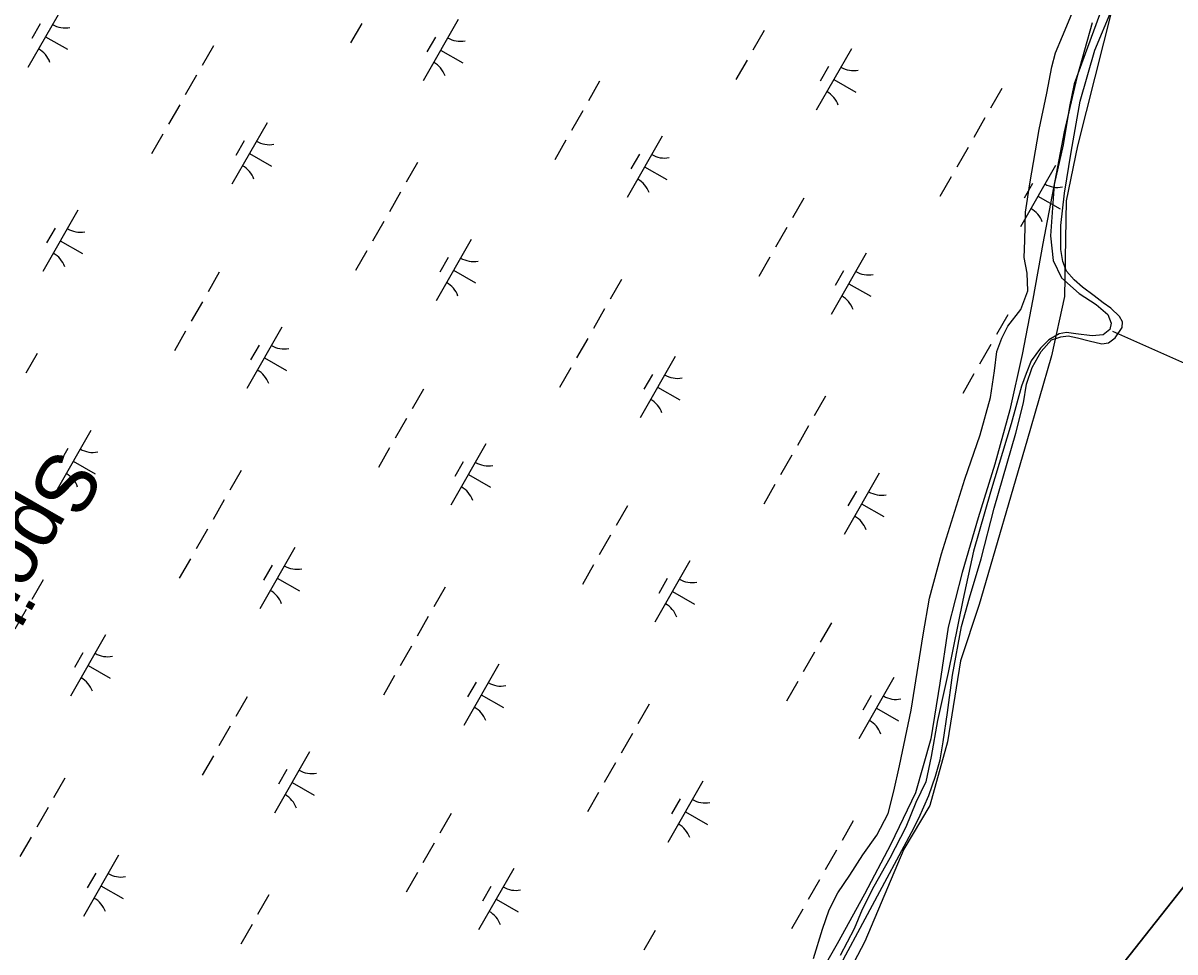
# Model space of a CAD drawing. Extents: x 3930721 to 3950824, y 220441 to 242861.
# Drawn here: x 3938674 to 3939489, y 229321 to 229978 of the extents above; entities that cross this region are included whole.
import ezdxf

# ---------------------------------------------------------------- set-up
doc = ezdxf.new("R2010")
doc.units = 0
for name, color, linetype in [('V-CHAN-SPOL', 7, 'Continuous'), ('V-LEVE-TOET', 7, 'Continuous'), ('V-RIVR-EDGE', 7, 'Continuous'), ('V-RIVR-JETY', 7, 'Continuous'), ('V-RRAP-FSHR', 7, 'Continuous'), ('V-TOPO-DPTH', 7, 'Continuous'), ('V-TOPO-MINR', 7, 'Continuous'), ('V-WETL-SWMP', 7, 'Continuous')]:
    doc.layers.add(name, color=color, linetype=linetype)

msp = doc.modelspace()

# ---------------------------------------------------------------- linework, layer by layer
at = {"layer": 'V-LEVE-TOET'}
msp.add_lwpolyline([(3939445.14, 229760.37), (3939506.58, 229733.14), (3939560.07, 229712.49), (3939562.56, 229705.25), (3939824.79, 229580.15)], dxfattribs=at)
at = {"layer": 'V-RIVR-EDGE'}
msp.add_lwpolyline([(3939444.95, 229988.74), (3939420.38, 229891.49), (3939412.2, 229852.59), (3939411.17, 229785.02), (3939401.96, 229743.05), (3939384.56, 229682.65), (3939350.77, 229566.97), (3939337.46, 229527.05), (3939328.25, 229469.72), (3939315.97, 229424.68), (3939297.54, 229393.97), (3939269.9, 229328.45), (3939213.6, 229220.96)], dxfattribs=at)
at = {"layer": 'V-RIVR-JETY'}
for points in [[(3939311.08, 229545.58), (3939315.67, 229571.36), (3939324.13, 229602.94), (3939340.55, 229655.78), (3939351.43, 229687.07), (3939358.73, 229713.48), (3939361.57, 229732.28), (3939363.25, 229745.93), (3939366.79, 229755.35), (3939370.94, 229763.86), (3939380.2, 229775.76), (3939385.21, 229788.83), (3939384.79, 229801.54), (3939382.55, 229812.42), (3939383.04, 229824.54), (3939383.44, 229844.52), (3939386.57, 229864.54), (3939393.14, 229903.05), (3939398.63, 229928.84), (3939402.08, 229947.34), (3939404.7, 229957.36), (3939409.73, 229969.22), (3939418.6, 229990.5)], [(3939435.92, 229984.32), (3939427.37, 229961.22)], [(3939427.37, 229961.22), (3939417.94, 229935.39), (3939414.77, 229919.32), (3939410.2, 229892.32), (3939403.83, 229864.11), (3939401.17, 229827.75), (3939403.16, 229810.51), (3939409.04, 229798.16), (3939421.56, 229787.08), (3939433.45, 229779.33), (3939441.69, 229772.15), (3939444.18, 229766.12), (3939443.31, 229761.57), (3939438.51, 229757.89), (3939430.64, 229757.2), (3939419.12, 229758.6), (3939412.46, 229759.44), (3939407.32, 229758.48), (3939400.1, 229754.17), (3939394.1, 229748.36), (3939387.53, 229739.51), (3939383.99, 229730.39), (3939380.75, 229721.58), (3939373.45, 229694.86), (3939358.8, 229646.58), (3939346.81, 229604.68), (3939339.29, 229570.09), (3939328.91, 229518.82), (3939321.39, 229484.84), (3939316.8, 229459.36), (3939313.04, 229441.46), (3939305.93, 229426.86), (3939298.84, 229409.53), (3939287.55, 229387.61), (3939276.25, 229367.52), (3939267.94, 229351.09), (3939262.33, 229337.41), (3939252.53, 229318.54)], [(3939233.48, 229316.53), (3939239.93, 229337.18), (3939244.63, 229350.85), (3939250.87, 229363.02), (3939259.22, 229375.52), (3939268.46, 229389.84), (3939278.31, 229403.87), (3939286.33, 229419.09), (3939290.41, 229434.87), (3939294.46, 229452.78), (3939302.54, 229492.21), (3939311.08, 229545.58)]]:
    msp.add_lwpolyline(points, dxfattribs=at)
at = {"layer": 'V-RRAP-FSHR'}
msp.add_lwpolyline([(3939430.76, 229978.49), (3939419.93, 229940), (3939410.89, 229901.37), (3939403.33, 229861.82), (3939395.88, 229822.46), (3939388.63, 229783.13), (3939381.24, 229743.82), (3939372.45, 229704.81), (3939361.79, 229666.27), (3939350.14, 229628.4), (3939338.64, 229589.69), (3939328.76, 229550.95), (3939323, 229511.38), (3939316.65, 229471.92), (3939305.64, 229433.66), (3939288.17, 229397.51), (3939269.61, 229362.1), (3939250.3, 229326.97), (3939230.51, 229292.21)], dxfattribs=at)
at = {"layer": 'V-TOPO-DPTH'}
msp.add_lwpolyline([(3939138.35, 228899.83), (3939165.62, 228949.61), (3939838.21, 229801.24), (3940275.57, 230709.64), (3940672.35, 231617.74), (3940572.03, 231858.55), (3940567.32, 231867.07), (3940561.52, 231871.8), (3940554.1, 231870.85), (3940545.59, 231866.11), (3940533.62, 231848.45), (3940521.9, 231830.62), (3940510.57, 231812.55), (3940499.49, 231794.3), (3940485.98, 231771.51), (3940470.36, 231745.8), (3940454.38, 231720.33), (3940437.86, 231695.21), (3940420.97, 231670.32), (3940394.26, 231631.89), (3940546.87, 231888.16), (3940838.91, 231677.12)], dxfattribs=at)
at = {"layer": 'V-TOPO-MINR'}
msp.add_lwpolyline([(3940394.26, 231631.89), (3940420.97, 231670.32), (3940437.86, 231695.21), (3940454.38, 231720.33), (3940470.36, 231745.8), (3940485.98, 231771.51), (3940499.49, 231794.3), (3940510.57, 231812.55), (3940521.9, 231830.62), (3940533.62, 231848.45), (3940545.59, 231866.11), (3940554.1, 231870.85), (3940561.52, 231871.8), (3940567.32, 231867.07), (3940572.03, 231858.55), (3940672.35, 231617.74), (3940275.57, 230709.64), (3939838.21, 229801.24), (3939165.62, 228949.61), (3939138.35, 228899.83)], dxfattribs=at)
at = {"layer": 'V-WETL-SWMP'}
for p, q in [((3938702.67, 229990.48), (3938677.82, 229947.09)), ((3938982.2, 229981.03), (3938957.35, 229937.64)), ((3939432.52, 229959.27), (3939444.71, 229987.99)), ((3938686.53, 229977.83), (3938680.56, 229967.42)), ((3938914.08, 229978.21), (3938906.13, 229964.33)), ((3939198.58, 229973.1), (3939190.63, 229959.22)), ((3938690.24, 229968.79), (3938705.86, 229959.84)), ((3938966.06, 229968.37), (3938960.1, 229957.96)), ((3938809.04, 229962.32), (3938801.08, 229948.43)), ((3938969.78, 229959.33), (3938985.4, 229950.39)), ((3939260.41, 229960.25), (3939235.56, 229916.86)), ((3939422.23, 229923.04), (3939432.52, 229959.27)), ((3939186.65, 229952.27), (3939178.7, 229938.39)), ((3938797.11, 229941.49), (3938789.16, 229927.61)), ((3939244.27, 229947.6), (3939238.31, 229937.19)), ((3939082.27, 229937.2), (3939074.32, 229923.32)), ((3939247.98, 229938.56), (3939263.6, 229929.61)), ((3939366.78, 229932.09), (3939358.83, 229918.2)), ((3938785.18, 229920.66), (3938777.23, 229906.78)), ((3939070.35, 229916.37), (3939062.4, 229902.49)), ((3939415.84, 229887.1), (3939422.23, 229923.04)), ((3938847.01, 229907.82), (3938822.16, 229864.43)), ((3939354.85, 229911.26), (3939346.9, 229897.38)), ((3938773.25, 229899.84), (3938765.3, 229885.95)), ((3938830.87, 229895.16), (3938824.91, 229884.75)), ((3939058.42, 229895.55), (3939050.47, 229881.66)), ((3939126.54, 229898.36), (3939101.69, 229854.97)), ((3938834.58, 229886.12), (3938850.2, 229877.18)), ((3939110.4, 229885.71), (3939104.44, 229875.29)), ((3939342.92, 229890.43), (3939334.97, 229876.55)), ((3939411.21, 229857.99), (3939415.84, 229887.1)), ((3938953.38, 229879.65), (3938945.43, 229865.77)), ((3939114.12, 229876.67), (3939129.74, 229867.72)), ((3939404.75, 229877.59), (3939379.9, 229834.2)), ((3939331, 229869.61), (3939323.04, 229855.72)), ((3938941.45, 229858.82), (3938933.5, 229844.94)), ((3939388.61, 229864.93), (3939382.65, 229854.52)), ((3939226.62, 229854.53), (3939218.66, 229840.65)), ((3939392.33, 229855.89), (3939407.95, 229846.95)), ((3939408.59, 229835.08), (3939411.21, 229857.99)), ((3938713.14, 229845.92), (3938688.29, 229802.54)), ((3938929.52, 229838), (3938921.57, 229824.11)), ((3939214.69, 229833.71), (3939206.74, 229819.82)), ((3939408.5, 229818.18), (3939408.59, 229835.08)), ((3938697, 229833.27), (3938691.04, 229822.86)), ((3938700.72, 229824.23), (3938716.34, 229815.29)), ((3938991.35, 229825.15), (3938966.5, 229781.76)), ((3939409.88, 229809.62), (3939408.5, 229818.18)), ((3938917.59, 229817.17), (3938909.64, 229803.29)), ((3938975.21, 229812.5), (3938969.25, 229802.08)), ((3939202.76, 229812.88), (3939194.81, 229799)), ((3939270.88, 229815.69), (3939246.03, 229772.31)), ((3939412.55, 229802.89), (3939409.88, 229809.62)), ((3938813.21, 229802.1), (3938805.26, 229788.21)), ((3938978.92, 229803.46), (3938994.54, 229794.51)), ((3939254.75, 229803.04), (3939248.78, 229792.63)), ((3939418.07, 229796.7), (3939412.55, 229802.89)), ((3939097.72, 229796.98), (3939089.77, 229783.1)), ((3939258.46, 229794), (3939274.08, 229785.06)), ((3939423.85, 229791.56), (3939418.07, 229796.7)), ((3939432.23, 229785.41), (3939423.85, 229791.56)), ((3939438.51, 229780.53), (3939432.23, 229785.41)), ((3938801.29, 229781.27), (3938793.33, 229767.39)), ((3939444.01, 229776.69), (3939438.51, 229780.53)), ((3939450.05, 229770.77), (3939444.01, 229776.69)), ((3939085.79, 229776.16), (3939077.84, 229762.27)), ((3939370.96, 229771.87), (3939363.01, 229757.98)), ((3939452.17, 229766.89), (3939450.05, 229770.77)), ((3938789.36, 229760.45), (3938781.41, 229746.56)), ((3938857.48, 229763.26), (3938832.63, 229719.87)), ((3939447.08, 229755.67), (3939451.95, 229762.99)), ((3939451.95, 229762.99), (3939452.17, 229766.89)), ((3939073.86, 229755.33), (3939065.91, 229741.45)), ((3939394.67, 229746.04), (3939401.87, 229754.17)), ((3939401.87, 229754.17), (3939408.6, 229756.32)), ((3939408.6, 229756.32), (3939413.79, 229757.15)), ((3939413.79, 229757.15), (3939420.31, 229755.65)), ((3939420.31, 229755.65), (3939428.65, 229753.66)), ((3939428.65, 229753.66), (3939437.51, 229751.41)), ((3939437.51, 229751.41), (3939442.18, 229752.24)), ((3939442.18, 229752.24), (3939447.08, 229755.67)), ((3938684.32, 229744.55), (3938676.37, 229730.66)), ((3938841.34, 229750.61), (3938835.38, 229740.19)), ((3939359.03, 229751.04), (3939351.08, 229737.16)), ((3939388.29, 229734.79), (3939394.67, 229746.04)), ((3938845.06, 229741.56), (3938860.68, 229732.62)), ((3939135.69, 229742.48), (3939110.84, 229699.1)), ((3939061.94, 229734.5), (3939053.98, 229720.62)), ((3939119.55, 229729.83), (3939113.59, 229719.42)), ((3939347.1, 229730.22), (3939339.15, 229716.33)), ((3939384.25, 229722.79), (3939388.29, 229734.79)), ((3939123.27, 229720.79), (3939138.89, 229711.84)), ((3939382.04, 229709.77), (3939384.25, 229722.79)), ((3938957.56, 229719.43), (3938949.6, 229705.55)), ((3939242.06, 229714.32), (3939234.11, 229700.43)), ((3939376.8, 229688.14), (3939382.04, 229709.77)), ((3938945.63, 229698.61), (3938937.68, 229684.72)), ((3938722.29, 229690.05), (3938697.44, 229646.66)), ((3939230.13, 229693.49), (3939222.18, 229679.61)), ((3939361.48, 229635.22), (3939376.8, 229688.14)), ((3939001.82, 229680.59), (3938976.97, 229637.2)), ((3938706.15, 229677.39), (3938700.19, 229666.98)), ((3938933.7, 229677.78), (3938925.75, 229663.9)), ((3939218.21, 229672.66), (3939210.25, 229658.78)), ((3938709.86, 229668.35), (3938725.48, 229659.41)), ((3938985.68, 229667.94), (3938979.72, 229657.53)), ((3938828.66, 229661.88), (3938820.71, 229648)), ((3938989.4, 229658.9), (3939005.02, 229649.95)), ((3939280.03, 229659.82), (3939255.18, 229616.43)), ((3939206.28, 229651.84), (3939198.33, 229637.95)), ((3939263.89, 229647.16), (3939257.93, 229636.75)), ((3938816.73, 229641.05), (3938808.78, 229627.17)), ((3939267.61, 229638.12), (3939283.23, 229629.18)), ((3939101.9, 229636.77), (3939093.95, 229622.88)), ((3939352.22, 229599.25), (3939361.48, 229635.22)), ((3938804.8, 229620.23), (3938796.85, 229606.34)), ((3939089.97, 229615.94), (3939082.02, 229602.06)), ((3938866.63, 229607.38), (3938841.78, 229563.99)), ((3938792.88, 229599.4), (3938784.92, 229585.52)), ((3939146.16, 229597.93), (3939121.32, 229554.54)), ((3939343.93, 229571.61), (3939352.22, 229599.25)), ((3938850.49, 229594.73), (3938844.53, 229584.31)), ((3939078.04, 229595.11), (3939070.09, 229581.23)), ((3938688.5, 229584.33), (3938680.54, 229570.45)), ((3938854.21, 229585.69), (3938869.83, 229576.74)), ((3939130.03, 229585.27), (3939124.06, 229574.86)), ((3938973, 229579.21), (3938965.05, 229565.33)), ((3939133.74, 229576.23), (3939149.36, 229567.29)), ((3939338.15, 229551.54), (3939343.93, 229571.61)), ((3938676.57, 229563.5), (3938668.62, 229549.62)), ((3938961.07, 229558.39), (3938953.12, 229544.5)), ((3939246.24, 229554.1), (3939238.29, 229540.22)), ((3939332, 229516.9), (3939338.15, 229551.54)), ((3938732.76, 229545.49), (3938707.91, 229502.1)), ((3938716.62, 229532.84), (3938710.66, 229522.42)), ((3938949.14, 229537.56), (3938941.19, 229523.68)), ((3939234.31, 229533.27), (3939226.36, 229519.39)), ((3939010.97, 229524.72), (3938986.12, 229481.33)), ((3938720.34, 229523.8), (3938735.96, 229514.85)), ((3938937.22, 229516.74), (3938929.27, 229502.85)), ((3939328.37, 229490.61), (3939332, 229516.9)), ((3938994.83, 229512.06), (3938988.87, 229501.65)), ((3939222.38, 229512.45), (3939214.43, 229498.56)), ((3939290.51, 229515.26), (3939265.66, 229471.87)), ((3938832.84, 229501.66), (3938824.89, 229487.78)), ((3938998.55, 229503.02), (3939014.17, 229494.08)), ((3939274.37, 229502.61), (3939268.4, 229492.19)), ((3939117.34, 229496.55), (3939109.39, 229482.66)), ((3939278.08, 229493.57), (3939293.7, 229484.62)), ((3939325.2, 229469.78), (3939328.37, 229490.61)), ((3938820.91, 229480.84), (3938812.96, 229466.95)), ((3939105.41, 229475.72), (3939097.46, 229461.84)), ((3939323.25, 229457.02), (3939325.2, 229469.78)), ((3938808.98, 229460.01), (3938801.03, 229446.13)), ((3938877.1, 229462.82), (3938852.26, 229419.44)), ((3939093.49, 229454.9), (3939085.53, 229441.01)), ((3939319.98, 229445.55), (3939323.25, 229457.02)), ((3938703.94, 229444.11), (3938695.99, 229430.23)), ((3938860.97, 229450.17), (3938855, 229439.76)), ((3939315.19, 229431.72), (3939319.98, 229445.55)), ((3938864.68, 229441.13), (3938880.3, 229432.18)), ((3939155.31, 229442.05), (3939130.46, 229398.66)), ((3939081.56, 229434.07), (3939073.61, 229420.19)), ((3939139.18, 229429.4), (3939133.21, 229418.98)), ((3939308.07, 229415.79), (3939315.19, 229431.72)), ((3938692.01, 229423.29), (3938684.06, 229409.4)), ((3938977.18, 229419), (3938969.23, 229405.11)), ((3939142.89, 229420.35), (3939158.51, 229411.41)), ((3939261.68, 229413.88), (3939253.73, 229400)), ((3939302.97, 229405.6), (3939308.07, 229415.79)), ((3938680.08, 229402.46), (3938672.13, 229388.58)), ((3939231.02, 229272.04), (3939302.97, 229405.6)), ((3938965.25, 229398.17), (3938957.3, 229384.29)), ((3938741.91, 229389.61), (3938717.06, 229346.22)), ((3939249.76, 229393.06), (3939241.8, 229379.17)), ((3938953.32, 229377.35), (3938945.37, 229363.46)), ((3939021.45, 229380.16), (3938996.6, 229336.77)), ((3938725.77, 229376.96), (3938719.81, 229366.55)), ((3939237.83, 229372.23), (3939229.88, 229358.35)), ((3938729.49, 229367.92), (3938745.11, 229358.97)), ((3938848.28, 229361.45), (3938840.33, 229347.56)), ((3939005.31, 229367.5), (3938999.34, 229357.09)), ((3939009.02, 229358.46), (3939024.64, 229349.52)), ((3939225.9, 229351.4), (3939217.95, 229337.52)), ((3938836.35, 229340.62), (3938828.4, 229326.74)), ((3939121.52, 229336.33), (3939113.57, 229322.45))]:
    msp.add_line(p, q, dxfattribs=at)
for centre, start, end in [((3938704.17, 229992.64), 239.42788, 280.97154), ((3938983.71, 229983.18), 239.42788, 280.97154), ((3938676.72, 229944.7), 19.42788, 60.97154), ((3938956.25, 229935.25), 19.42788, 60.97154), ((3939261.92, 229962.41), 239.42788, 280.97154), ((3939234.46, 229914.47), 19.42788, 60.97154), ((3938848.52, 229909.97), 239.42788, 280.97154), ((3939128.05, 229900.52), 239.42788, 280.97154), ((3938821.06, 229862.03), 19.42788, 60.97154), ((3939100.6, 229852.58), 19.42788, 60.97154), ((3939406.26, 229879.74), 239.42788, 280.97154), ((3939378.8, 229831.81), 19.42788, 60.97154), ((3938714.65, 229848.08), 239.42788, 280.97154), ((3938687.19, 229800.14), 19.42788, 60.97154), ((3938992.86, 229827.31), 239.42788, 280.97154), ((3939272.39, 229817.85), 239.42788, 280.97154), ((3938965.4, 229779.37), 19.42788, 60.97154), ((3939244.94, 229769.91), 19.42788, 60.97154), ((3938858.99, 229765.42), 239.42788, 280.97154), ((3938831.54, 229717.48), 19.42788, 60.97154), ((3939137.2, 229744.64), 239.42788, 280.97154), ((3939109.74, 229696.7), 19.42788, 60.97154), ((3938723.8, 229692.2), 239.42788, 280.97154), ((3939003.33, 229682.75), 239.42788, 280.97154), ((3938696.34, 229644.27), 19.42788, 60.97154), ((3938975.88, 229634.81), 19.42788, 60.97154), ((3939281.54, 229661.97), 239.42788, 280.97154), ((3939254.09, 229614.04), 19.42788, 60.97154), ((3938868.14, 229609.54), 239.42788, 280.97154), ((3939147.67, 229600.08), 239.42788, 280.97154), ((3938840.68, 229561.6), 19.42788, 60.97154), ((3939120.22, 229552.15), 19.42788, 60.97154), ((3938734.27, 229547.65), 239.42788, 280.97154), ((3938706.82, 229499.71), 19.42788, 60.97154), ((3939012.48, 229526.87), 239.42788, 280.97154), ((3939292.01, 229517.42), 239.42788, 280.97154), ((3938985.03, 229478.93), 19.42788, 60.97154), ((3939264.56, 229469.48), 19.42788, 60.97154), ((3938878.61, 229464.98), 239.42788, 280.97154), ((3938851.16, 229417.04), 19.42788, 60.97154), ((3939156.82, 229444.21), 239.42788, 280.97154), ((3939129.37, 229396.27), 19.42788, 60.97154), ((3938743.42, 229391.77), 239.42788, 280.97154), ((3939022.95, 229382.31), 239.42788, 280.97154), ((3938715.97, 229343.83), 19.42788, 60.97154), ((3938995.5, 229334.38), 19.42788, 60.97154)]:
    msp.add_arc(centre, 17.62, start, end, dxfattribs=at)

# ---------------------------------------------------------------- texts
at = {"layer": 'V-CHAN-SPOL'}
msp.add_text('Spoil', height=42, rotation=240.18996, dxfattribs=at).set_placement((3938696.16, 229679.22))

doc.saveas('drawing.dxf')
